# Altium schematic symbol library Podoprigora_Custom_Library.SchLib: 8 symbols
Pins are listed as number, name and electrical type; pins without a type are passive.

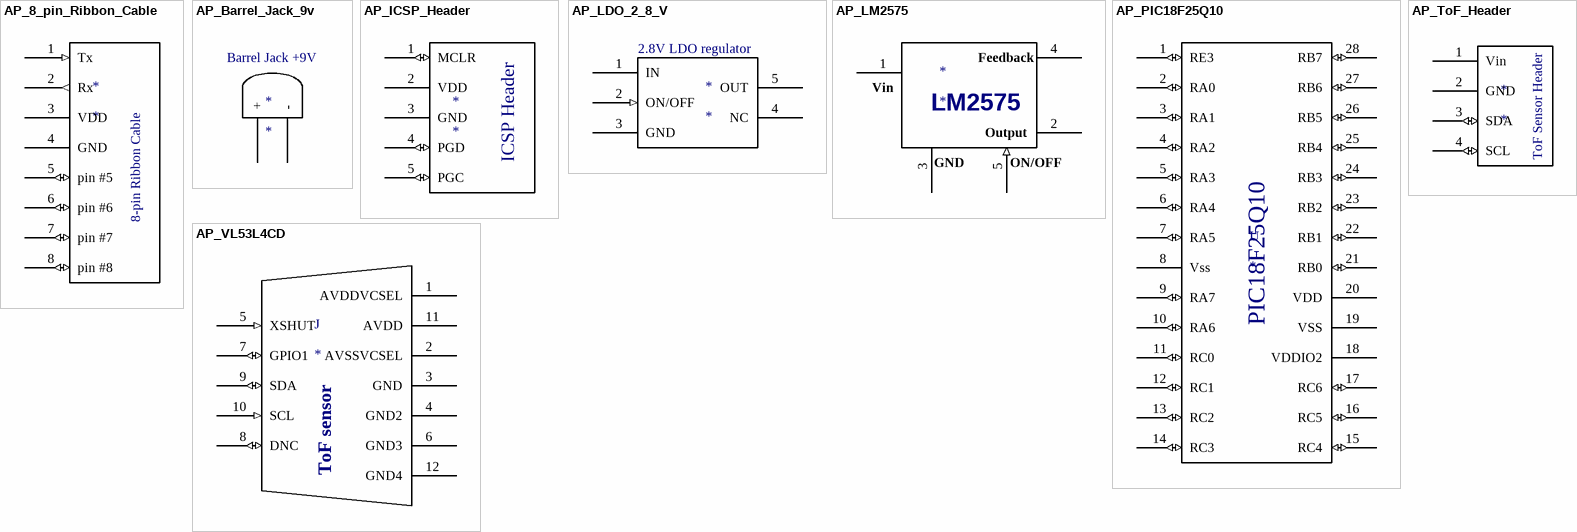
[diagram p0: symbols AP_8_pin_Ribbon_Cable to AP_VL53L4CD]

## AP_8_pin_Ribbon_Cable
designator *
pins: 1 Tx (in), 2 Rx (out), 3 VDD (power), 4 GND (power), 5 pin #5 (io), 6 pin #6 (io), 7 pin #7 (io), 8 pin #8 (io)

## AP_Barrel_Jack_9v
designator *
pins: 1 + (power), 1 - (power)

## AP_ICSP_Header
designator *
Header for the Microchip Snap
pins: 1 MCLR (io), 2 VDD (power), 3 GND (power), 4 PGD (io), 5 PGC (io)

## AP_LDO_2_8_V
designator *
pins: 1 IN (power), 2 ON/OFF (in), 3 GND (power), 4 NC, 5 OUT (power)

## AP_LM2575
designator *
pins: 1 Vin, 2 Output, 3 GND, 4 Feedback, 5 ON/OFF (in)

## AP_PIC18F25Q10
designator U
PIC18F25Q10 represented as a library element
pins: 1 RE3 (io), 2 RA0 (io), 3 RA1 (io), 4 RA2 (io), 5 RA3 (io), 6 RA4 (io), 7 RA5 (io), 8 Vss (power), 9 RA7 (io), 10 RA6 (io), 11 RC0 (io), 12 RC1 (io), 13 RC2 (io), 14 RC3 (io), 15 RC4 (io), 16 RC5 (io), 17 RC6 (io), 18 VDDIO2 (power), 19 VSS (power), 20 VDD, 21 RB0 (io), 22 RB1 (io), 23 RB2 (io), 24 RB3 (io), 25 RB4 (io), 26 RB5 (io), 27 RB6 (io), 28 RB7 (io)

## AP_ToF_Header
designator *
pins: 1 Vin, 2 GND, 3 SDA (io), 4 SCL (io)

## AP_VL53L4CD
designator J
Tof sensor type VL53L4CD
pins: 1 AVDDVCSEL (power), 2 AVSSVCSEL (power), 3 GND (power), 4 GND2 (power), 5 XSHUT (in), 6 GND3 (power), 7 GPIO1 (io), 8 DNC (io), 9 SDA (io), 10 SCL (in), 11 AVDD (power), 12 GND4 (power)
